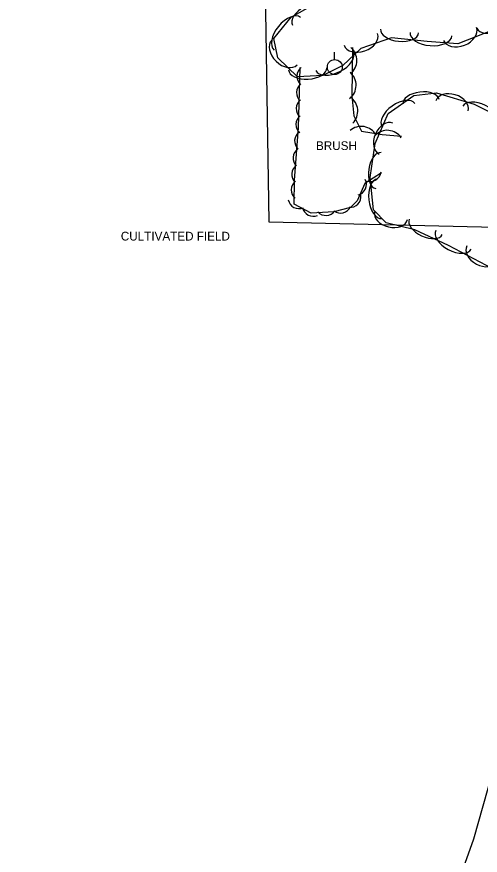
# Model space of a CAD drawing. Extents: x 1802180 to 1804859, y 572524 to 575172.
# Drawn here: x 1803144.4 to 1803276.9, y 573350.8 to 573590.8 of the extents above; entities that cross this region are included whole.
import ezdxf

# ---------------------------------------------------------------- set-up
doc = ezdxf.new("R2010")
doc.units = 0
for name, color, linetype in [('S_MISC_BOUNDARY', 7, 'Continuous'), ('S_MISC_BOUNDARY_ANNOT', 7, 'Continuous'), ('S_TREE', 7, 'Continuous'), ('S_TREE_ANNOT', 7, 'Continuous'), ('S_UTILITY_POLE', 7, 'Continuous')]:
    doc.layers.add(name, color=color, linetype=linetype)

msp = doc.modelspace()

# ---------------------------------------------------------------- linework, layer by layer
at = {"layer": 'S_MISC_BOUNDARY'}
msp.add_lwpolyline([(1802880.88, 573735.6), (1803051.71, 573733.48), (1803213.27, 573730.83), (1803216.46, 573532.09), (1803301.63, 573530.07), (1803296.75, 573432.28), (1803274.96, 573355.36), (1803226.68, 573219.53), (1803202.19, 573137.5), (1803157.77, 572977.33), (1803158.5, 572726.69), (1802889.88, 572728.1)], dxfattribs=at)
at = {"layer": 'S_TREE'}
for points in [[(1803297.38, 573598.34), (1803285.61, 573588.98), (1803270.5, 573583.07), (1803261.74, 573583.77), (1803251.55, 573584.8), (1803242.81, 573581.77), (1803237.61, 573576.86), (1803231.85, 573573.98), (1803224.66, 573573.6), (1803219, 573579.07), (1803217.88, 573584.63), (1803222.81, 573590.7), (1803232.15, 573596.04)], [(1803240.37, 573582.04), (1803240.16, 573568.23), (1803240.74, 573562.45), (1803243, 573558.11), (1803248.86, 573557.12), (1803254.37, 573556.61)], [(1803248.71, 573546.17), (1803243.9, 573543.09), (1803241.68, 573538.18), (1803239.78, 573536.2), (1803235.03, 573534.95), (1803228.57, 573534.58), (1803223.66, 573537.14), (1803223.76, 573544.01), (1803224.98, 573559.04), (1803225.43, 573576.32)], [(1803280.53, 573518.65), (1803267.83, 573525.39), (1803258.24, 573529.86), (1803250.01, 573531.84), (1803246.42, 573535.52), (1803245.43, 573544.81), (1803246.87, 573554.59), (1803250.59, 573563.16), (1803257.91, 573568.32), (1803264.37, 573569.09), (1803275.17, 573565.85), (1803286.31, 573560.18), (1803298.09, 573549.26), (1803301.58, 573537.69), (1803299.74, 573530.34), (1803296.47, 573524.33), (1803289.21, 573519.84), (1803283.69, 573519.21), (1803280.53, 573518.65)]]:
    msp.add_lwpolyline(points, dxfattribs=at)
for centre, radius, start, end in [((1803236.77, 573578.33), 4.85, 308.3649, 49.9618), ((1803227.64, 573573.82), 3.15, 127.6897, 229.2866), ((1803236.56, 573571.22), 4.85, 308.3649, 49.9618), ((1803227.51, 573569.12), 3.15, 127.6897, 229.2866), ((1803237.04, 573563.8), 4.85, 314.8704, 56.4673), ((1803227.42, 573564.54), 3.15, 127.6897, 229.2866), ((1803227.36, 573559.98), 3.15, 127.6897, 229.2866), ((1803226.98, 573555.26), 3.15, 124.5799, 226.1768), ((1803242.88, 573554.59), 4.85, 29.5998, 131.1967), ((1803250.3, 573553.47), 4.85, 33.8531, 135.4501), ((1803226.56, 573550.4), 3.15, 124.5799, 226.1768), ((1803226.17, 573545.71), 3.15, 124.5799, 226.1768), ((1803245.41, 573546.79), 3.15, 251.8603, 353.4573), ((1803226.02, 573541.28), 3.15, 128.3593, 229.9562), ((1803241.2, 573542.85), 3.15, 284.8702, 26.4671), ((1803225.09, 573539.05), 3.15, 191.6696, 293.2665), ((1803239.66, 573539.4), 3.15, 265.4988, 7.0957), ((1803229.15, 573536.87), 3.15, 191.6696, 293.2665), ((1803236.93, 573537.79), 3.15, 233.9145, 335.5114), ((1803232.77, 573537.09), 3.15, 222.5065, 324.1034)]:
    msp.add_arc(centre, radius, start, end, dxfattribs=at)
for centre, major_axis, ratio in [((1803228.01, 573591.17), (-4.75, -2.72), 0.540699), ((1803221.76, 573585.97), (-3.79, -4.67), 0.55008), ((1803281.06, 573589.53), (5.1, 2), 0.540699), ((1803253.85, 573586.76), (5.45, -0.55), 0.540699), ((1803271.13, 573585.93), (4.73, 1.85), 0.685311), ((1803220.93, 573580.6), (3.65, -3.53), 0.685311), ((1803242.75, 573584.34), (4.8, 1.66), 0.685311), ((1803262.84, 573585.86), (5.99, -0.48), 0.55008), ((1803235.26, 573578.11), (5.38, 2.69), 0.55008), ((1803227.55, 573575.93), (5.47, 0.29), 0.540699), ((1803259.96, 573566.48), (-5.17, -0.62), 0.540699), ((1803253.53, 573562.7), (-4.67, -3.29), 0.55008), ((1803268.83, 573565.33), (-4.62, 1.39), 0.685311), ((1803277, 573562.6), (-5.1, 2.59), 0.55008), ((1803249.97, 573555.92), (-1.93, -4.43), 0.685311), ((1803247.81, 573546.78), (-0.76, -5.16), 0.540699), ((1803248.16, 573538.72), (0.61, -5.69), 0.55008), ((1803251.41, 573533.89), (4.7, -1.13), 0.685311), ((1803261.34, 573530.69), (4.72, -2.2), 0.540699), ((1803269.26, 573526.97), (5.05, -2.68), 0.55008), ((1803277.35, 573522.97), (4.27, -2.26), 0.685311)]:
    msp.add_ellipse(centre, major_axis=major_axis, ratio=ratio, start_param=3.141593, end_param=6.283185, dxfattribs=at)
at = {"layer": 'S_UTILITY_POLE'}
msp.add_line((1803235.19, 573578.57), (1803235.19, 573580.68), dxfattribs=at)
msp.add_circle((1803235.32, 573576.43), 2.13, dxfattribs=at)

# ---------------------------------------------------------------- texts
at = {"layer": 'S_MISC_BOUNDARY_ANNOT'}
msp.add_text('CULTIVATED FIELD', height=2.5, dxfattribs=at).set_placement((1803174.12, 573526.77))
at = {"layer": 'S_TREE_ANNOT'}
msp.add_text('BRUSH', height=2.5, dxfattribs=at).set_placement((1803229.94, 573552.68))

doc.saveas('drawing.dxf')
